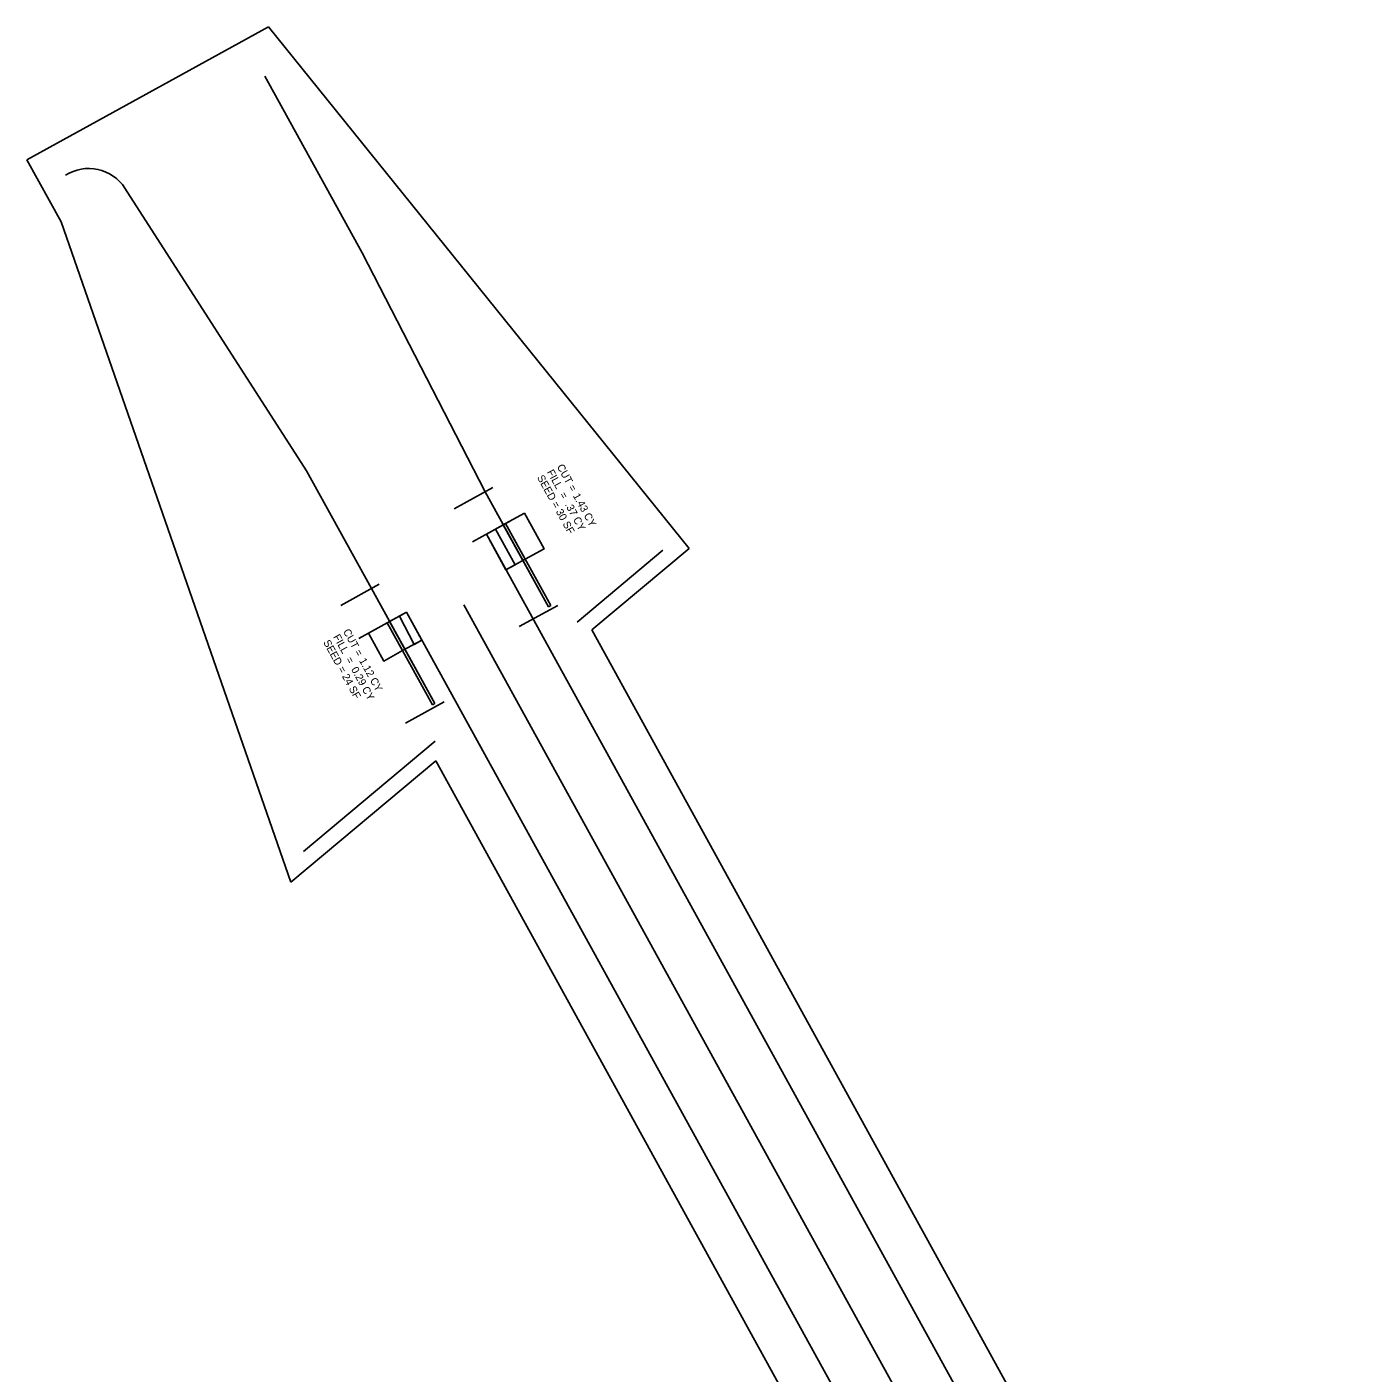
# Model space of a CAD drawing. Extents: x 1494134 to 1494615, y 514855 to 515612.
# Drawn here: x 1494133.6 to 1494382.2, y 515361.3 to 515611.7 of the extents above; entities that cross this region are included whole.
import ezdxf

# ---------------------------------------------------------------- set-up
doc = ezdxf.new("R2010")
doc.units = 0
for name, color, linetype in [('BR_P_Rail_Object', 7, 'Continuous'), ('BR_P_Slab_Const_Joint', 7, 'Continuous'), ('BR_P_Slab_Object', 7, 'Continuous'), ('BR_P_Sub_Object', 7, 'Continuous'), ('BR_X_Rail_Object', 7, 'Continuous'), ('BR_X_Sub_Foot_Hidden', 7, 'Continuous'), ('PV_P_Curb', 7, 'Continuous'), ('RW_X_CL', 7, 'Continuous'), ('RW_X_Fee_WL', 7, 'Continuous'), ('SC_Scratch2', 7, 'Continuous'), ('SV_P_Control_Cells_Set', 7, 'Continuous')]:
    doc.layers.add(name, color=color, linetype=linetype)

msp = doc.modelspace()

# ---------------------------------------------------------------- linework, layer by layer
at = {"layer": 'BR_P_Rail_Object'}
for p, q in [((1494235.89, 515501.03), (1494251.85, 515514.41)), ((1494185, 515458.36), (1494209.47, 515478.88))]:
    msp.add_line(p, q, dxfattribs=at)
at = {"layer": 'BR_P_Slab_Const_Joint'}
for p, q in [((1494222.58, 515519.34), (1494226.23, 515512.71)), ((1494220.69, 515518.29), (1494224.34, 515511.67)), ((1494202.85, 515502.15), (1494205.56, 515496.88)), ((1494200.58, 515500.9), (1494197.08, 515498.97)), ((1494197.08, 515498.97), (1494199.93, 515493.78)), ((1494199.93, 515493.78), (1494203.44, 515495.71))]:
    msp.add_line(p, q, dxfattribs=at)
for points in [[(1494219.01, 515517.37), (1494222.58, 515519.34), (1494226.23, 515512.71), (1494222.65, 515510.74)], [(1494222.58, 515519.34), (1494226.09, 515521.26), (1494229.74, 515514.64), (1494226.23, 515512.71)], [(1494224.34, 515511.67), (1494222.65, 515510.74), (1494219.01, 515517.37), (1494220.69, 515518.29)], [(1494204.16, 515502.87), (1494207.01, 515497.68), (1494203.44, 515495.71), (1494200.58, 515500.9)], [(1494204.16, 515502.87), (1494207.01, 515497.68), (1494205.56, 515496.88), (1494202.85, 515502.15)], [(1494203.44, 515495.71), (1494199.93, 515493.78), (1494197.08, 515498.97), (1494200.58, 515500.9)]]:
    msp.add_lwpolyline(points, close=True, dxfattribs=at)
msp.add_lwpolyline([(1494222.58, 515519.34), (1494226.09, 515521.26), (1494229.74, 515514.64), (1494226.23, 515512.71)], dxfattribs=at)
at = {"layer": 'BR_P_Slab_Object'}
for p, q in [((1494219.01, 515517.37), (1494379.7, 515225.45)), ((1494204.16, 515502.87), (1494362.18, 515215.81))]:
    msp.add_line(p, q, dxfattribs=at)
at = {"layer": 'BR_P_Sub_Object'}
msp.add_line((1494214.83, 515504.21), (1494370.94, 515220.63), dxfattribs=at)
at = {"layer": 'BR_X_Rail_Object'}
for p, q in [((1494178.49, 515611.71), (1494133.57, 515586.99)), ((1494178.49, 515611.71), (1494256.7, 515514.73)), ((1494133.57, 515586.99), (1494139.92, 515575.46)), ((1494139.92, 515575.46), (1494182.65, 515452.65)), ((1494256.7, 515514.73), (1494238.61, 515499.56)), ((1494238.61, 515499.56), (1494382.22, 515238.67)), ((1494182.65, 515452.65), (1494209.58, 515475.23)), ((1494353.16, 515214.38), (1494209.58, 515475.23))]:
    msp.add_line(p, q, dxfattribs=at)
at = {"layer": 'BR_X_Sub_Foot_Hidden'}
for p, q in [((1494222.65, 515510.74), (1494219.01, 515517.37)), ((1494207.01, 515497.68), (1494204.16, 515502.87))]:
    msp.add_line(p, q, dxfattribs=at)
at = {"layer": 'PV_P_Curb'}
for p, q in [((1494222.58, 515519.34), (1494222.15, 515519.09)), ((1494230.53, 515503.86), (1494222.15, 515519.09)), ((1494230.97, 515504.1), (1494222.58, 515519.34)), ((1494230.97, 515504.1), (1494230.53, 515503.86)), ((1494201.02, 515501.14), (1494200.58, 515500.9)), ((1494208.97, 515485.66), (1494200.58, 515500.9)), ((1494209.41, 515485.9), (1494201.02, 515501.14)), ((1494209.41, 515485.9), (1494208.97, 515485.66))]:
    msp.add_line(p, q, dxfattribs=at)
at = {"layer": 'RW_X_CL'}
msp.add_line((1494151.77, 515581.74), (1494185.59, 515529.17), dxfattribs=at)
msp.add_arc((1494145.08, 515577.43), 7.96, 32.7551, 122.7551, dxfattribs=at)
at = {"layer": 'RW_X_Fee_WL'}
for p, q in [((1494222.15, 515519.09), (1494219.01, 515517.37)), ((1494201.02, 515501.14), (1494204.16, 515502.87))]:
    msp.add_line(p, q, dxfattribs=at)
at = {"layer": 'SC_Scratch2'}
for p, q in [((1494220.23, 515526.03), (1494213.05, 515522.08)), ((1494223.61, 515519.9), (1494216.43, 515515.95)), ((1494199.1, 515508.08), (1494191.92, 515504.12)), ((1494232.29, 515504.13), (1494225.11, 515500.18)), ((1494202.48, 515501.94), (1494195.3, 515497.99)), ((1494211.16, 515486.18), (1494203.98, 515482.22))]:
    msp.add_line(p, q, dxfattribs=at)
at = {"layer": 'SV_P_Control_Cells_Set'}
for p, q in [((1494177.82, 515602.56), (1494195.9, 515569.7)), ((1494195.9, 515569.7), (1494218.77, 515525.23)), ((1494197.64, 515507.27), (1494185.59, 515529.17)), ((1494218.77, 515525.23), (1494230.53, 515503.86)), ((1494209.41, 515485.9), (1494197.64, 515507.27))]:
    msp.add_line(p, q, dxfattribs=at)

# ---------------------------------------------------------------- texts
at = {"layer": 'BR_P_Slab_Const_Joint'}
for s, p in [('FILL  =  .37 CY', (1494230.23, 515528.93)), ('CUT =', (1494232.07, 515529.94)), ('SEED = 30 SF', (1494228.39, 515527.92)), (' 1.43 CY', (1494234.8, 515524.98)), ('CUT =', (1494192.31, 515499.3)), ('SEED = 24 SF', (1494188.63, 515497.27)), ('FILL  =  0.29 CY', (1494190.47, 515498.29)), (' 1.12 CY', (1494195.04, 515494.33))]:
    msp.add_text(s, height=1.4, rotation=298.8312, dxfattribs=at).set_placement(p)

doc.saveas('drawing.dxf')
